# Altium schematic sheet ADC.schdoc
size 297 x 209 mm; Symbol: Drawing-Symbol_A4; @Project Name: Pedal Steel; @Page Count: 1; @Update Date: 2026-10-20; @Create Date: 2026-10-20; @Schematic Name: Schematic1; @Page No: 1; @Page Name: P1; Company: EasyEDA.com; Version: V1.0; Page Size: A4; Device: Drawing-Symbol_A4; @Create Time: 16:29:24; @Update Time: 16:29:24; Border: 1; Width: 1170; Height: 825; Region Start: 1; X Region Count: 6; Y Region Count: 4; Blade Width: 10; Title Block Position: 3
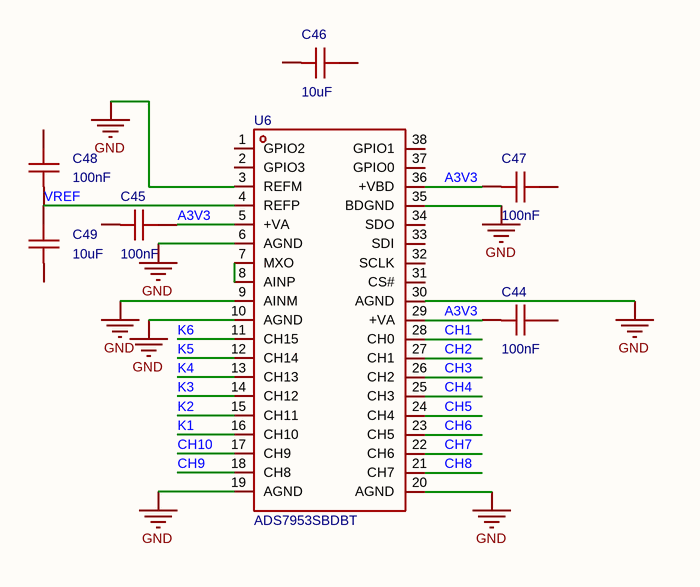
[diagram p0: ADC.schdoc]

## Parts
C44  100nF  [C0603]
C45  100nF  [C0603]
C46  10uF  [C0603]
C47  100nF  [C0603]
C48  100nF  [C0603]
C49  10uF  [C0603]
U6  ADS7953SBDBT  [TSSOP-38_L9.7-W4.4-P0.50-LS6.4-BL]

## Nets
GND: U6.3(REFM) U6.6(AGND) U6.9(AINM) U6.10(AGND) U6.19(AGND) U6.20(AGND) U6.30(AGND) U6.35(BDGND)
A3V3: C44.2 C45.1 C47.2 U6.5(+VA) U6.29(+VA) U6.36(+VBD)
CH1: U6.28(CH0)
CH2: U6.27(CH1)
CH3: U6.26(CH2)
CH4: U6.25(CH3)
CH5: U6.24(CH4)
CH6: U6.23(CH5)
CH7: U6.22(CH6)
CH8: U6.21(CH7)
CH9: U6.18(CH8)
CH10: U6.17(CH9)
K1: U6.16(CH10)
K2: U6.15(CH11)
K3: U6.14(CH12)
K4: U6.13(CH13)
K5: U6.12(CH14)
K6: U6.11(CH15)
VREF: C48.2 C49.1 U6.4(REFP)
NetU6_7: U6.7(MXO) U6.8(AINP)

Not connected (* = marked no-connect by the designer): C44 1; C45 2; C46 1 2; C47 1; C48 1; C49 2; U6 1(GPIO2) 2(GPIO3) 31(CS#) 32(SCLK) 33(SDI) 34(SDO) 37(GPIO0) 38(GPIO1)

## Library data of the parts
C44-C49 = CAP_0603: Symbol: CAP_OLD; ConvertToPcb: yes; ModelId: 624118aa3cc7497086c383c2d72e08520819f05c4eef4c71ace90d822a990e87; ModelName: C0603_L1.6-W0.8-H0.8; ModelTransform: 62.992,31.496,0,0,0,0,0,0,0
U6 = ADS7953SBDBT: Resolution (Bits):12 Sampling Rate:1MHz number of channels:16 Voltage - Supply:2.7V~5.25V Voltage - Supply:2.7V~5.25V Interface:Serial port differential input:No Integral non - linearity:0.5LSB Integral non - linearity:0.5LSB Operating Temperature:-40℃~+1; Manufacturer: TI(德州仪器); AddInBom: yes; ModelId: 4c1db536ed5641bf81ee274c95a6a2500819f05c4eef4c71ace90d822a990e87; ModelName: TSSOP-38_L9.7-W4.4-H1.0-LS6.4-P0.50; ModelTransform: 381.889,251.968,0,0,0,0,0,0,0; Resolution (Bits): 12; Sampling Rate: 1MHz; number of channels: 16; differential input: No; Integral non - linearity: 0.5LSB; Signal-to-Noise Ratio: 71.7dB; Clock Frequency: 20MHz; ADC architecture: SAR; Quiescent Current (Iq): 3mA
